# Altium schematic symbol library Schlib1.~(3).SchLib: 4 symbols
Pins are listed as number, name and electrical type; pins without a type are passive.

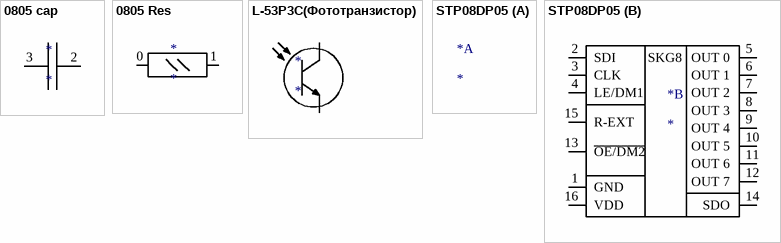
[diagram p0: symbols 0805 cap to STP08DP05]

## 0805 cap
designator *
pins: 2, 3

## 0805 Res
designator *
pins: 0, 1

## L-53P3C(Фототранзистор)
designator *

## STP08DP05
designator *
part B pins: 1 GND, 2 SDI, 3 CLK, 4 LE/DM1, 5 OUT 0, 6 OUT 1, 7 OUT 2, 8 OUT 3, 9 OUT 4, 10 OUT 5, 11 OUT 6, 12 OUT 7, 13 ~{OE/DM2}, 14 SDO, 15 R-EXT, 16 VDD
